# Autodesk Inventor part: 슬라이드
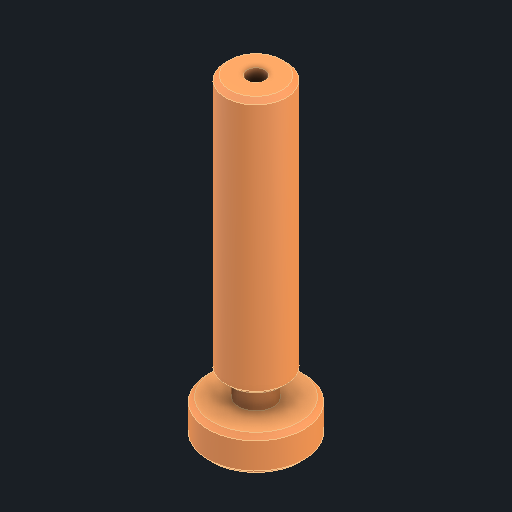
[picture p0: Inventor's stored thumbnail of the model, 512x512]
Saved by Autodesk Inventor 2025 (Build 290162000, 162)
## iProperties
Created: 2025-08
Part Number: 슬라이드
Material: 강철, 연강
Document SubType Name: Modeling
Designer: infra11
Density: 7.86 g/cm^3
Appearance: 기본값
Author: jhkim
Sending System: Autodesk Inventor 2026
Preprocessor: ST-DEVELOPER v20.1
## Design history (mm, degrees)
feature "솔리드1"
node "솔리드2"
